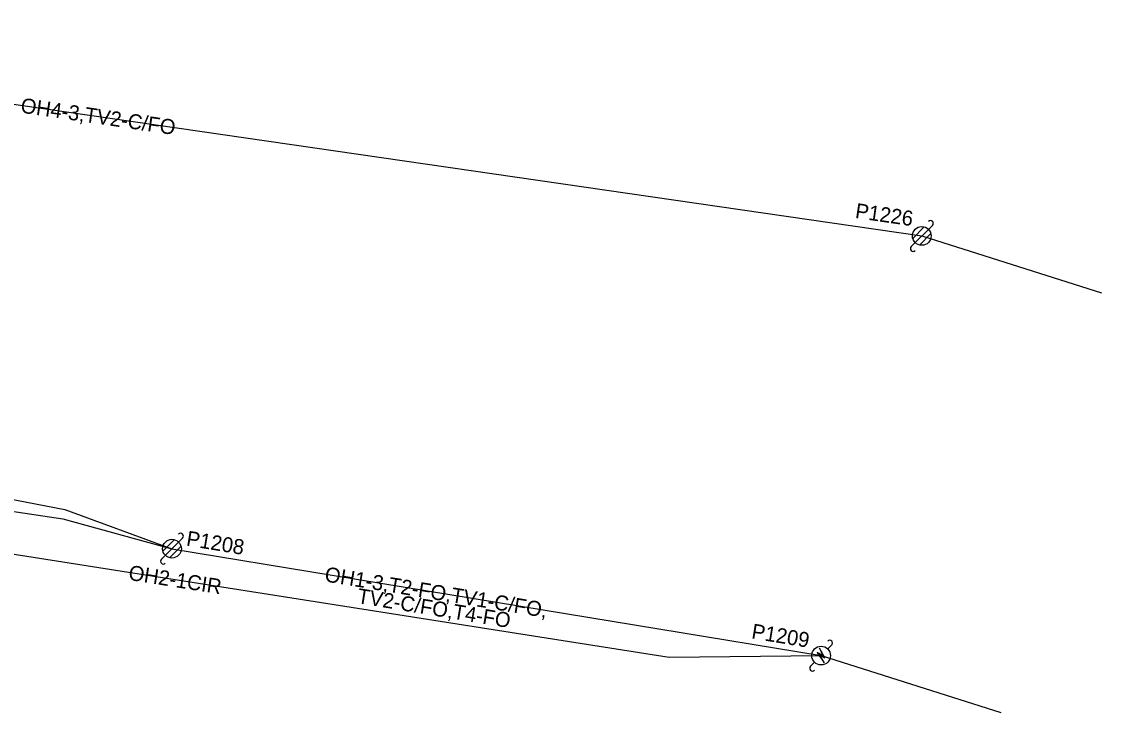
# Model space of a CAD drawing. Extents: x 2336688 to 2352634, y 362473 to 369571.
# Drawn here: x 2352345.9 to 2352634, y 368822.9 to 369007.1 of the extents above; entities that cross this region are included whole.
import ezdxf

# ---------------------------------------------------------------- set-up
doc = ezdxf.new("R2010")
doc.units = 0
for name, color, linetype in [('RD_EX_DV_TX_Prop', 7, 'Continuous'), ('RD_HC_Data_Tic', 7, 'Continuous'), ('RD_PD_Final_TrvlWay', 7, 'Continuous'), ('RD_PD_PatLn4', 7, 'Continuous'), ('RD_SHT_ShtClip', 7, 'Continuous')]:
    doc.layers.add(name, color=color, linetype=linetype)

msp = doc.modelspace()

# ---------------------------------------------------------------- linework, layer by layer
at = {"layer": 'RD_HC_Data_Tic'}
for p, q in [((2352583.66, 368949.25), (2352586.73, 368952.31)), ((2352584.31, 368948.13), (2352587.85, 368951.66)), ((2352587.85, 368951.66), (2352588.91, 368952.72)), ((2352583.25, 368947.07), (2352584.31, 368948.13)), ((2352585.43, 368947.48), (2352588.49, 368950.54)), ((2352383.6, 368865.87), (2352386.66, 368868.93)), ((2352384.25, 368864.75), (2352387.78, 368868.28)), ((2352387.78, 368868.28), (2352388.84, 368869.34)), ((2352383.18, 368863.68), (2352384.25, 368864.75)), ((2352385.37, 368864.1), (2352388.43, 368867.16)), ((2352560.97, 368839.77), (2352562.03, 368840.83)), ((2352556.38, 368835.17), (2352557.44, 368836.23))]:
    msp.add_line(p, q, dxfattribs=at)
msp.add_lwpolyline([(2352558.81, 368840.01), (2352559.64, 368837.99), (2352558.18, 368838.8), (2352560.06, 368836.11), (2352560.06, 368836.11), (2352558.86, 368838.21), (2352560.24, 368837.41)], close=True, dxfattribs=at)
for centre in [(2352586.08, 368949.9), (2352386.01, 368866.51), (2352559.21, 368838)]:
    msp.add_circle(centre, 2.5, dxfattribs=at)
for centre, start, end in [((2352588.38, 368953.25), 315, 135), ((2352583.78, 368946.54), 135, 315), ((2352388.31, 368869.87), 315, 135), ((2352383.71, 368863.15), 135, 315), ((2352561.5, 368841.36), 315, 135), ((2352556.91, 368834.64), 135, 315)]:
    msp.add_arc(centre, 0.75, start, end, dxfattribs=at)
at = {"layer": 'RD_PD_Final_TrvlWay'}
for points in [[(2352218.4, 368898.75), (2352248.79, 368897.87), (2352252.62, 368897.13), (2352253.71, 368894.06), (2352257.36, 368896.22), (2352357.47, 368876.97), (2352386.01, 368866.51)], [(2352253.13, 368886.52), (2352283.32, 368885.51), (2352356.87, 368874.44), (2352386.01, 368866.51)]]:
    msp.add_lwpolyline(points, dxfattribs=at)
at = {"layer": 'RD_SHT_ShtClip'}
for p, q in [((2352192.38, 369007.05), (2352586.08, 368949.9)), ((2352586.08, 368949.9), (2352634, 368934.75)), ((2352386.01, 368866.51), (2352559.21, 368838)), ((2352559.21, 368838), (2352607.13, 368822.86))]:
    msp.add_line(p, q, dxfattribs=at)
msp.add_lwpolyline([(2352233.45, 368889.14), (2352271.93, 368876.31), (2352518.65, 368837.57), (2352559.21, 368838)], dxfattribs=at)

# ---------------------------------------------------------------- texts
at = {"layer": 'RD_EX_DV_TX_Prop'}
for s, rotation, p in [('P1226', 351.7393, (2352568.14, 368954.72)), ('P1208', 350.6509, (2352389.66, 368867.37)), ('P1209', 350.6509, (2352540.46, 368842.61))]:
    msp.add_text(s, height=4, rotation=rotation, dxfattribs=at).set_placement(p)
at = {"layer": 'RD_PD_PatLn4'}
for s, rotation, p in [('OH4-3,TV2-C/FO', 351.7149, (2352345.46, 368982.81)), ('OH2-1CIR', 351.058, (2352374.23, 368858.23)), ('OH1-3,T2-FO,TV1-C/FO,', 350.6509, (2352426.57, 368857.81)), ('TV2-C/FO,T4-FO', 350.6509, (2352435.25, 368852.04))]:
    msp.add_text(s, height=4, rotation=rotation, dxfattribs=at).set_placement(p)

doc.saveas('drawing.dxf')
